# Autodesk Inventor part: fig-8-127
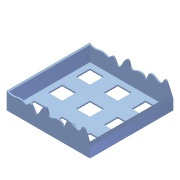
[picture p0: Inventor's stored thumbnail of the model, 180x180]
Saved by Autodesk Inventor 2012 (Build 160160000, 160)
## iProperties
Shininess: 64.0
Length Units: 11269
Angle Units: 11279
Time Units: 11290
Mass Units: 11283
Length Display Precision: 3
Angle Display Precision: 2
Compacted: True
Part Number: fig-8-127
Document SubType Name: Modeling
Created: 2002-12
Designer: deepak
Density: 1 g/cm^3
Material: Default
Density: 0.0
Volumn: 0.0
Area: 0.0
PropertySet Name: Model Information
Control State: 0
Master: False
Checked Out: False
Author: deepak
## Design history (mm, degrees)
sketch "Sketch1"
  geometry: L1 (-32.188, 30.089)-(27.812, 30.089); L2 (27.812, 30.089)-(27.812, -29.911); L3 (27.812, -29.911)-(-32.188, -29.911); L4 (-32.188, -29.911)-(-32.188, 30.089)
  constraints: 8 end point, 2 parallel, 1 horizontal, 1 perpendicular
  dimensions: "d0" = 60 distance of L1.start L1.end; "d1" = 60 distance of L3.end L1.start
extrude "Extrusion1" new body sketch "Sketch1" stored distance "d2" = 20; taper "d3" = 0 deg
shell "Shell2" dims "d21" = 1
sketch "Sketch5"
  geometry: L1 (-27.812, 30.089)-(32.188, 30.089) reference; L2 (-27.812, -29.911)-(-27.812, 30.089) reference; L3 (-22.812, 25.089)-(-12.812, 25.089); L4 (-12.812, 25.089)-(-12.812, 15.089); L5 (-12.812, 15.089)-(-22.812, 15.089); L6 (-22.812, 15.089)-(-22.812, 25.089)
  constraints: 8 end point, 2 parallel, 1 horizontal, 1 perpendicular
  dimensions: "d8" = 10 distance of L3.start L3.end; "d9" = 10 distance of L5.end L3.start; "d10" = 5 distance between parallel lines of L2 L6; "d11" = 5 distance between parallel lines of L1 L3
extrude "Extrusion2" cut sketch "Sketch5" distance "d12" = 50; taper "d13" = 0 deg
pattern_linear "Rectangular Pattern1" dims "d16" = 20
sketch "Sketch2"
  geometry: 17 further points
  constraints: 17 other
extrude_surface "ExtrusionSrf1" sketch "Sketch2" dims "d4" = 70, "d5" = 0
split "Split2"
body "Solid1"
body "Srf1"
